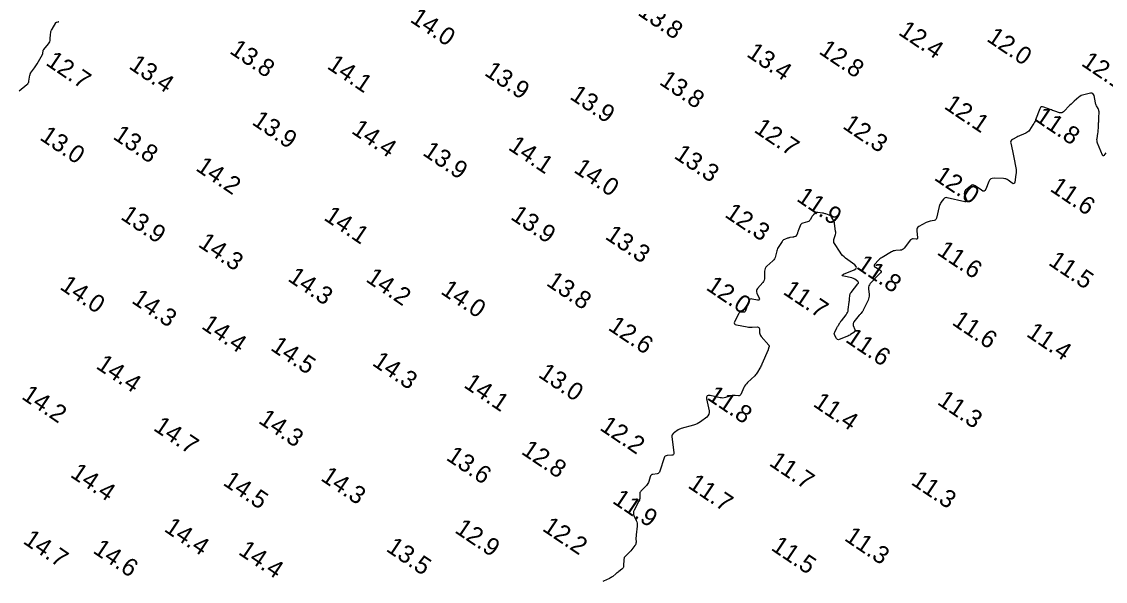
# Model space of a CAD drawing. Extents: x 815352 to 820877, y 582403 to 597439.
# Drawn here: x 816560.4 to 816866.2, y 584040.7 to 584198.7 of the extents above; entities that cross this region are included whole.
import ezdxf

# ---------------------------------------------------------------- set-up
doc = ezdxf.new("R2010")
doc.units = 0
doc.layers.add('V-CONT-EL12', color=7, linetype='Continuous')
doc.layers.add('V-TOPO-SOUN', color=7, linetype='Continuous')

msp = doc.modelspace()

# ---------------------------------------------------------------- linework, layer by layer
at = {"layer": 'V-CONT-EL12'}
for points in [[(816559.72, 584179.16), (816561.95, 584180.99), (816562.15, 584181.19), (816562.31, 584181.41), (816562.43, 584181.66), (816562.5, 584181.94), (816562.78, 584183.57), (816562.79, 584183.62), (816562.8, 584183.67), (816562.81, 584183.73), (816562.82, 584183.78), (816562.88, 584184), (816562.9, 584184.05), (816562.92, 584184.1), (816562.95, 584184.15), (816562.98, 584184.19), (816564.1, 584185.69), (816564.3, 584185.96), (816564.48, 584186.23), (816564.66, 584186.51), (816564.82, 584186.8), (816566.3, 584189.43), (816566.35, 584189.54), (816566.39, 584189.65), (816566.42, 584189.77), (816566.44, 584189.89), (816566.48, 584190.38), (816566.5, 584190.5), (816566.53, 584190.62), (816566.59, 584190.72), (816566.66, 584190.82), (816568, 584192.44), (816568.21, 584192.74), (816568.36, 584193.05), (816568.46, 584193.39), (816568.51, 584193.75), (816568.6, 584195.22), (816568.64, 584195.58), (816568.72, 584195.93), (816568.85, 584196.27), (816569.02, 584196.6), (816570.1, 584198.42), (816570.15, 584198.49), (816570.21, 584198.54), (816570.28, 584198.57), (816570.37, 584198.6), (816570.72, 584198.65), (816570.8, 584198.67), (816570.87, 584198.71), (816570.92, 584198.77)], [(816866.4, 584161.66), (816865.85, 584160.95), (816865.72, 584160.82), (816865.61, 584160.79), (816865.5, 584160.85), (816865.42, 584161.01), (816864.07, 584164.4), (816863.96, 584164.73), (816863.9, 584165.07), (816863.89, 584165.41), (816863.92, 584165.76), (816864.13, 584167.15), (816864.18, 584167.5), (816864.22, 584167.85), (816864.25, 584168.2), (816864.28, 584168.55), (816864.36, 584170.1), (816864.38, 584170.47), (816864.39, 584170.83), (816864.41, 584171.2), (816864.42, 584171.56), (816864.46, 584173.29), (816864.45, 584173.51), (816864.41, 584173.73), (816864.34, 584173.95), (816864.24, 584174.15), (816863.78, 584174.96), (816863.67, 584175.16), (816863.58, 584175.37), (816863.51, 584175.59), (816863.46, 584175.81), (816863.06, 584177.84), (816862.93, 584178.19), (816862.72, 584178.42), (816862.44, 584178.52), (816862.06, 584178.49), (816860.2, 584178.09), (816859.8, 584177.98), (816859.43, 584177.83), (816859.08, 584177.62), (816858.75, 584177.37), (816857.49, 584176.27), (816857.18, 584175.99), (816856.87, 584175.71), (816856.57, 584175.42), (816856.27, 584175.13), (816854.46, 584173.29), (816854.2, 584173.09), (816853.93, 584172.98), (816853.63, 584172.95), (816853.31, 584173.01), (816852, 584173.44), (816851.67, 584173.55), (816851.34, 584173.66), (816851.02, 584173.78), (816850.7, 584173.9), (816848.91, 584174.61), (816848.54, 584174.7), (816848.22, 584174.65), (816847.97, 584174.45), (816847.78, 584174.12), (816846.56, 584171.03), (816846.4, 584170.65), (816846.22, 584170.29), (816846.03, 584169.93), (816845.82, 584169.58), (816844.87, 584168.12), (816844.67, 584167.84), (816844.42, 584167.6), (816844.14, 584167.41), (816843.83, 584167.25), (816842.51, 584166.71), (816842.19, 584166.57), (816841.87, 584166.42), (816841.55, 584166.27), (816841.24, 584166.1), (816840.01, 584165.43), (816839.76, 584165.24), (816839.59, 584165), (816839.53, 584164.73), (816839.56, 584164.41), (816840.04, 584162.26), (816840.15, 584161.79), (816840.25, 584161.32), (816840.34, 584160.84), (816840.43, 584160.37), (816840.97, 584157.4), (816841.04, 584156.93), (816841.06, 584156.46), (816841.05, 584155.99), (816841, 584155.52), (816840.69, 584153.41), (816840.6, 584153.12), (816840.46, 584152.98), (816840.25, 584152.97), (816839.99, 584153.11), (816838.81, 584153.96), (816838.51, 584154.15), (816838.19, 584154.29), (816837.85, 584154.38), (816837.49, 584154.42), (816834.86, 584154.52), (816834.35, 584154.47), (816833.93, 584154.3), (816833.6, 584153.99), (816833.35, 584153.54), (816832.5, 584151.44), (816832.28, 584151.06), (816832.01, 584150.88), (816831.68, 584150.89), (816831.29, 584151.09), (816829.51, 584152.38), (816829.16, 584152.57), (816828.82, 584152.62), (816828.49, 584152.53), (816828.17, 584152.31), (816826.82, 584151.11), (816826.59, 584150.83), (816826.46, 584150.54), (816826.44, 584150.22), (816826.52, 584149.87), (816827.06, 584148.42), (816827.13, 584148.12), (816827.07, 584147.92), (816826.89, 584147.84), (816826.58, 584147.87), (816821.62, 584149.01), (816821.32, 584149.04), (816821.06, 584148.99), (816820.83, 584148.85), (816820.62, 584148.64), (816819.87, 584147.62), (816819.69, 584147.36), (816819.55, 584147.08), (816819.44, 584146.79), (816819.35, 584146.49), (816818.63, 584143.27), (816818.54, 584143.02), (816818.39, 584142.82), (816818.19, 584142.68), (816817.94, 584142.6), (816816.8, 584142.37), (816816.53, 584142.31), (816816.25, 584142.22), (816815.99, 584142.12), (816815.73, 584141.99), (816813.66, 584140.9), (816813.35, 584140.68), (816813.14, 584140.41), (816813.03, 584140.08), (816813.02, 584139.7), (816813.24, 584137.67), (816813.24, 584137.48), (816813.17, 584137.36), (816813.05, 584137.29), (816812.86, 584137.29), (816812.01, 584137.38), (816811.8, 584137.38), (816811.62, 584137.33), (816811.46, 584137.24), (816811.31, 584137.09), (816809.46, 584134.74), (816809.24, 584134.51), (816808.99, 584134.34), (816808.71, 584134.23), (816808.39, 584134.18), (816807.09, 584134.09), (816806.76, 584134.05), (816806.45, 584133.98), (816806.15, 584133.86), (816805.87, 584133.72), (816803.23, 584132.15), (816802.93, 584131.96), (816802.65, 584131.75), (816802.39, 584131.52), (816802.15, 584131.26), (816801.21, 584130.21), (816801.04, 584129.96), (816801.01, 584129.74), (816801.12, 584129.53), (816801.36, 584129.35), (816802.64, 584128.65), (816802.89, 584128.47), (816803, 584128.27), (816802.96, 584128.04), (816802.78, 584127.79), (816799.92, 584124.76), (816799.67, 584124.44), (816799.5, 584124.09), (816799.42, 584123.72), (816799.41, 584123.31), (816799.56, 584121.64), (816799.58, 584121.22), (816799.53, 584120.82), (816799.43, 584120.43), (816799.28, 584120.04), (816797.95, 584117.29), (816797.88, 584117.15), (816797.8, 584117.02), (816797.72, 584116.9), (816797.62, 584116.78), (816797.22, 584116.31), (816797.12, 584116.19), (816797.02, 584116.07), (816796.92, 584115.95), (816796.82, 584115.83), (816795.29, 584113.93), (816795.14, 584113.7), (816795.06, 584113.45), (816795.06, 584113.19), (816795.13, 584112.91), (816795.57, 584111.78), (816795.63, 584111.53), (816795.6, 584111.31), (816795.49, 584111.11), (816795.29, 584110.95), (816794.34, 584110.34), (816794.1, 584110.2), (816793.85, 584110.06), (816793.6, 584109.94), (816793.34, 584109.84), (816791.13, 584108.98), (816790.91, 584108.92), (816790.71, 584108.95), (816790.54, 584109.06), (816790.39, 584109.24), (816789.88, 584110.14), (816789.79, 584110.37), (816789.75, 584110.6), (816789.78, 584110.83), (816789.87, 584111.05), (816790.52, 584112.3), (816790.61, 584112.47), (816790.71, 584112.64), (816790.81, 584112.81), (816790.91, 584112.98), (816791.32, 584113.64), (816791.42, 584113.81), (816791.53, 584113.97), (816791.65, 584114.13), (816791.77, 584114.28), (816793.09, 584115.93), (816793.33, 584116.27), (816793.51, 584116.62), (816793.64, 584117.01), (816793.72, 584117.41), (816793.97, 584119.48), (816794, 584119.71), (816794.03, 584119.95), (816794.05, 584120.19), (816794.07, 584120.42), (816794.15, 584121.38), (816794.19, 584121.61), (816794.25, 584121.82), (816794.35, 584122.03), (816794.48, 584122.22), (816796.45, 584124.71), (816796.55, 584124.9), (816796.58, 584125.08), (816796.51, 584125.24), (816796.36, 584125.39), (816795.57, 584125.98), (816795.37, 584126.12), (816795.16, 584126.23), (816794.93, 584126.32), (816794.7, 584126.38), (816792.45, 584126.84), (816792.11, 584126.95), (816791.98, 584127.07), (816792.08, 584127.22), (816792.39, 584127.39), (816795.35, 584128.66), (816795.84, 584128.95), (816796.03, 584129.27), (816795.92, 584129.63), (816795.51, 584130.03), (816792.97, 584131.94), (816792.52, 584132.31), (816792.1, 584132.71), (816791.73, 584133.15), (816791.39, 584133.62), (816789.81, 584136.06), (816789.67, 584136.32), (816789.6, 584136.6), (816789.6, 584136.88), (816789.66, 584137.17), (816790.03, 584138.35), (816790.11, 584138.65), (816790.15, 584138.95), (816790.16, 584139.25), (816790.13, 584139.55), (816789.83, 584141.69), (816789.78, 584141.94), (816789.71, 584142.17), (816789.62, 584142.41), (816789.51, 584142.63), (816788.99, 584143.52), (816788.85, 584143.72), (816788.69, 584143.88), (816788.5, 584144.01), (816788.29, 584144.1), (816787.37, 584144.42), (816787.14, 584144.5), (816786.9, 584144.56), (816786.67, 584144.61), (816786.43, 584144.65), (816785.1, 584144.85), (816784.92, 584144.86), (816784.75, 584144.83), (816784.6, 584144.76), (816784.45, 584144.66), (816783.89, 584144.17), (816783.76, 584144.05), (816783.63, 584143.91), (816783.52, 584143.76), (816783.42, 584143.61), (816782.91, 584142.72), (816782.78, 584142.54), (816782.63, 584142.39), (816782.44, 584142.27), (816782.23, 584142.19), (816780.89, 584141.8), (816780.62, 584141.69), (816780.4, 584141.53), (816780.23, 584141.32), (816780.1, 584141.06), (816779.6, 584139.7), (816779.54, 584139.54), (816779.48, 584139.37), (816779.41, 584139.2), (816779.34, 584139.03), (816778.97, 584138.19), (816778.93, 584138.12), (816778.88, 584138.07), (816778.82, 584138.03), (816778.74, 584138.01), (816778.41, 584137.94), (816778.33, 584137.92), (816778.25, 584137.91), (816778.17, 584137.89), (816778.09, 584137.88), (816777.23, 584137.73), (816777.06, 584137.7), (816776.89, 584137.66), (816776.72, 584137.61), (816776.56, 584137.55), (816775.67, 584137.21), (816775.47, 584137.12), (816775.3, 584137), (816775.15, 584136.86), (816775.02, 584136.69), (816774.08, 584135.27), (816773.9, 584134.97), (816773.75, 584134.65), (816773.63, 584134.33), (816773.54, 584133.99), (816773.2, 584132.46), (816773.09, 584132.1), (816772.93, 584131.78), (816772.72, 584131.48), (816772.46, 584131.22), (816770.73, 584129.7), (816770.44, 584129.4), (816770.24, 584129.06), (816770.12, 584128.68), (816770.09, 584128.27), (816770.1, 584126.55), (816770.07, 584126.13), (816769.97, 584125.74), (816769.79, 584125.38), (816769.55, 584125.04), (816768.13, 584123.4), (816767.93, 584123.09), (816767.83, 584122.77), (816767.83, 584122.43), (816767.93, 584122.08), (816768.56, 584120.62), (816768.64, 584120.32), (816768.6, 584120.13), (816768.42, 584120.04), (816768.11, 584120.07), (816766.6, 584120.38), (816766.26, 584120.41), (816765.98, 584120.32), (816765.76, 584120.12), (816765.61, 584119.81), (816764.73, 584117.09), (816764.65, 584116.92), (816764.53, 584116.8), (816764.38, 584116.72), (816764.19, 584116.7), (816763.37, 584116.7), (816763.18, 584116.68), (816763.02, 584116.61), (816762.88, 584116.49), (816762.78, 584116.33), (816761.65, 584114.11), (816761.52, 584113.72), (816761.57, 584113.42), (816761.78, 584113.21), (816762.17, 584113.08), (816765.17, 584112.55), (816765.51, 584112.5), (816765.85, 584112.47), (816766.19, 584112.45), (816766.54, 584112.46), (816768.03, 584112.51), (816768.28, 584112.48), (816768.47, 584112.38), (816768.58, 584112.21), (816768.63, 584111.97), (816768.7, 584110.83), (816768.73, 584110.56), (816768.81, 584110.3), (816768.94, 584110.07), (816769.1, 584109.84), (816771.27, 584107.35), (816771.33, 584107.26), (816771.37, 584107.17), (816771.37, 584107.07), (816771.35, 584106.96), (816771.22, 584106.52), (816771.19, 584106.41), (816771.15, 584106.3), (816771.11, 584106.2), (816771.07, 584106.09), (816769.31, 584102), (816769.18, 584101.71), (816769.04, 584101.42), (816768.9, 584101.13), (816768.74, 584100.85), (816768.1, 584099.74), (816767.93, 584099.47), (816767.74, 584099.21), (816767.54, 584098.97), (816767.31, 584098.74), (816765.24, 584096.79), (816764.94, 584096.48), (816764.67, 584096.14), (816764.44, 584095.78), (816764.24, 584095.39), (816763.35, 584093.42), (816763.24, 584093.24), (816763.1, 584093.13), (816762.92, 584093.07), (816762.71, 584093.07), (816761.82, 584093.18), (816761.6, 584093.2), (816761.38, 584093.19), (816761.17, 584093.17), (816760.95, 584093.12), (816759.07, 584092.57), (816758.68, 584092.49), (816758.3, 584092.45), (816757.91, 584092.46), (816757.52, 584092.53), (816754.69, 584093.17), (816754.17, 584093.21), (816753.84, 584093.07), (816753.69, 584092.74), (816753.73, 584092.23), (816754.41, 584088.84), (816754.45, 584088.33), (816754.36, 584087.86), (816754.12, 584087.45), (816753.75, 584087.09), (816752, 584085.74), (816751.55, 584085.43), (816751.07, 584085.17), (816750.57, 584084.95), (816750.05, 584084.78), (816746.58, 584083.86), (816746.34, 584083.78), (816746.12, 584083.69), (816745.9, 584083.58), (816745.69, 584083.45), (816744.65, 584082.74), (816744.56, 584082.67), (816744.47, 584082.6), (816744.39, 584082.51), (816744.32, 584082.42), (816744.04, 584082.05), (816743.98, 584081.95), (816743.94, 584081.85), (816743.93, 584081.74), (816743.93, 584081.63), (816744.51, 584076.99), (816744.5, 584076.71), (816744.41, 584076.49), (816744.22, 584076.36), (816743.93, 584076.3), (816742.62, 584076.22), (816742.32, 584076.16), (816742.07, 584076.03), (816741.89, 584075.83), (816741.76, 584075.55), (816740.53, 584071.76), (816740.42, 584071.5), (816740.25, 584071.31), (816740.03, 584071.17), (816739.76, 584071.09), (816738.58, 584070.9), (816738.31, 584070.82), (816738.1, 584070.68), (816737.93, 584070.48), (816737.82, 584070.23), (816737.43, 584068.9), (816737.32, 584068.6), (816737.17, 584068.31), (816736.99, 584068.04), (816736.78, 584067.8), (816735.19, 584066.17), (816735.04, 584065.98), (816734.93, 584065.77), (816734.87, 584065.55), (816734.85, 584065.31), (816734.87, 584064.31), (816734.86, 584064.06), (816734.82, 584063.82), (816734.75, 584063.59), (816734.65, 584063.37), (816733.29, 584060.78), (816733.14, 584060.43), (816733.09, 584060.06), (816733.12, 584059.7), (816733.24, 584059.33), (816733.89, 584057.86), (816734.03, 584057.48), (816734.12, 584057.1), (816734.15, 584056.72), (816734.13, 584056.32), (816733.85, 584053.83), (816733.82, 584053.57), (816733.81, 584053.31), (816733.8, 584053.05), (816733.8, 584052.78), (816733.82, 584051.73), (816733.8, 584051.48), (816733.75, 584051.24), (816733.65, 584051.01), (816733.51, 584050.8), (816732.33, 584049.3), (816732.16, 584049.1), (816731.98, 584048.9), (816731.8, 584048.71), (816731.6, 584048.53), (816730.81, 584047.82), (816730.63, 584047.64), (816730.5, 584047.43), (816730.42, 584047.19), (816730.39, 584046.94), (816730.3, 584045), (816730.27, 584044.74), (816730.18, 584044.5), (816730.04, 584044.3), (816729.84, 584044.12), (816728.97, 584043.47), (816728.75, 584043.31), (816728.53, 584043.14), (816728.32, 584042.97), (816728.11, 584042.8), (816727.26, 584042.11), (816727.05, 584041.94), (816726.82, 584041.79), (816726.59, 584041.65), (816726.34, 584041.53), (816724.64, 584040.73), (816724.46, 584040.63)]]:
    msp.add_lwpolyline(points, dxfattribs=at)

# ---------------------------------------------------------------- texts
at = {"layer": 'V-TOPO-SOUN'}
for s, p in [('13.8 ', (816734.04, 584200.77)), ('14.0 ', (816669.8, 584198.84)), ('12.4 ', (816807.59, 584195.25)), ('12.0 ', (816832.5, 584193.43)), ('13.8 ', (816618.85, 584189.97)), ('13.4 ', (816764.75, 584189.09)), ('12.8 ', (816785.15, 584189.87)), ('12.7 ', (816566.98, 584186.66)), ('13.4 ', (816590.43, 584185.67)), ('14.1 ', (816646.37, 584185.68)), ('12.1 ', (816859.2, 584186.5)), ('13.9 ', (816690.76, 584183.8)), ('13.8 ', (816740.11, 584181.21)), ('13.9 ', (816714.84, 584177.11)), ('12.1 ', (816820.48, 584174.37)), ('13.9 ', (816625.15, 584169.89)), ('11.8 ', (816846.08, 584170.94)), ('14.4 ', (816653.23, 584167.43)), ('12.7 ', (816766.84, 584167.73)), ('12.3 ', (816791.84, 584168.78)), ('13.0 ', (816565.27, 584165.57)), ('13.8 ', (816585.94, 584165.82)), ('13.9 ', (816673.31, 584161.23)), ('14.1 ', (816697.48, 584162.78)), ('13.3 ', (816744.27, 584160.38)), ('14.2 ', (816609.3, 584156.9)), ('14.0 ', (816716, 584156.39)), ('12.0 ', (816817.67, 584154.22)), ('11.6 ', (816850.37, 584151.09)), ('11.9 ', (816778.85, 584148.3)), ('13.9 ', (816588.11, 584143.15)), ('14.1 ', (816645.45, 584142.94)), ('13.9 ', (816698.14, 584143.15)), ('12.3 ', (816758.58, 584143.78)), ('13.3 ', (816724.82, 584137.58)), ('14.3 ', (816609.99, 584135.41)), ('11.6 ', (816818.48, 584133.17)), ('11.5 ', (816849.92, 584130.23)), ('11.8 ', (816795.72, 584129.21)), ('14.3 ', (816635.28, 584125.73)), ('14.2 ', (816657.3, 584125.54)), ('13.8 ', (816708.22, 584124.45)), ('14.0 ', (816570.95, 584123.38)), ('14.0 ', (816678.43, 584122.1)), ('12.0 ', (816753.3, 584123.22)), ('11.7 ', (816775.05, 584121.99)), ('14.3 ', (816591.22, 584119.5)), ('14.4 ', (816610.91, 584112.28)), ('12.6 ', (816725.67, 584111.88)), ('11.6 ', (816822.72, 584113.36)), ('11.6 ', (816792.63, 584108.5)), ('11.4 ', (816843.71, 584110.08)), ('14.5 ', (816630.4, 584106.18)), ('14.4 ', (816581.15, 584101.03)), ('14.3 ', (816659.1, 584101.88)), ('13.0 ', (816705.96, 584098.58)), ('14.1 ', (816684.95, 584095.66)), ('14.2 ', (816560.15, 584092.43)), ('11.8 ', (816753.59, 584092.24)), ('11.4 ', (816783.51, 584090.33)), ('11.3 ', (816818.55, 584090.89)), ('14.3 ', (816626.98, 584085.61)), ('14.7 ', (816597.36, 584083.54)), ('12.2 ', (816723.31, 584083.64)), ('13.6 ', (816679.97, 584075.17)), ('12.8 ', (816701.16, 584076.88)), ('11.7 ', (816771.11, 584073.6)), ('14.4 ', (816573.9, 584070.38)), ('14.3 ', (816644.57, 584069.4)), ('14.5 ', (816616.98, 584068.09)), ('11.7 ', (816748.18, 584067.33)), ('11.3 ', (816811.17, 584068.25)), ('11.9 ', (816726.88, 584063)), ('14.4 ', (816600.38, 584055.03)), ('12.9 ', (816682.4, 584054.67)), ('12.2 ', (816707.1, 584055.19)), ('14.7 ', (816560.58, 584051.59)), ('11.3 ', (816792.34, 584052.44)), ('14.6 ', (816580.3, 584048.92)), ('14.4 ', (816621.34, 584048.53)), ('13.5 ', (816663.01, 584049.45)), ('11.5 ', (816771.63, 584049.75))]:
    msp.add_text(s, height=5, rotation=326, dxfattribs=at).set_placement(p)

doc.saveas('drawing.dxf')
